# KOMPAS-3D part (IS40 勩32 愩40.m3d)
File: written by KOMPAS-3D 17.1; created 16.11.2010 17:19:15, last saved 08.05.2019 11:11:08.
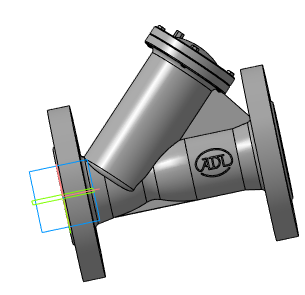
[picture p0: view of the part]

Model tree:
1. Плоскость XY
2. Плоскость ZX
3. Плоскость ZY
4. Ось X
5. Ось Y
6. Ось Z
7. Начало координат
8. Операция без истории:2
